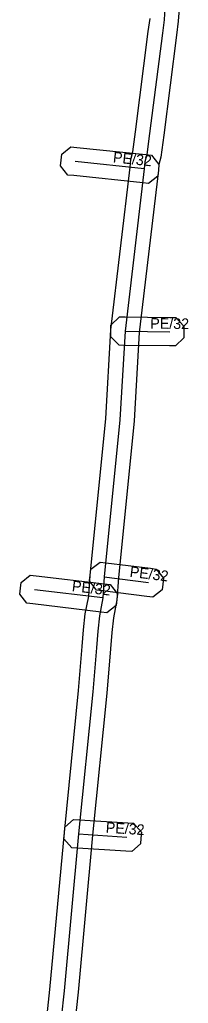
# Model space of a CAD drawing. Extents: x -772893 to -772575, y -1033735 to -1033288.
# Drawn here: x -772743.8 to -772731.9, y -1033432.5 to -1033363.2 of the extents above; entities that cross this region are included whole.
import ezdxf

# ---------------------------------------------------------------- set-up
doc = ezdxf.new("R2010")
doc.units = 0
for name, color, linetype in [('1', 7, 'Continuous'), ('24', 7, 'Continuous'), ('30', 7, 'Continuous')]:
    doc.layers.add(name, color=color, linetype=linetype)

msp = doc.modelspace()

# ---------------------------------------------------------------- linework, layer by layer
at = {"layer": '1'}
for points in [[(-772732.541, -1033362.417), (-772732.603, -1033363.282), (-772732.73, -1033364.269), (-772733.632, -1033371.329), (-772733.83, -1033372.876), (-772733.966, -1033373.389), (-772734.006, -1033373.796), (-772735.353, -1033385.227), (-772735.714, -1033391.464), (-772736.823, -1033402.543), (-772736.926, -1033404.078), (-772737.17, -1033405.353), (-772737.279, -1033406.391), (-772737.374, -1033407.541), (-772737.63, -1033410.653), (-772738.635, -1033420.686), (-772739.654, -1033431.747), (-772740.282, -1033437.549)], [(-772742.27, -1033437.333), (-772741.644, -1033431.547), (-772740.625, -1033420.494), (-772739.622, -1033410.471), (-772739.368, -1033407.377), (-772739.271, -1033406.203), (-772739.15, -1033405.059), (-772738.914, -1033403.822), (-772738.817, -1033402.377), (-772737.708, -1033391.306), (-772737.347, -1033385.053), (-772735.994, -1033373.584), (-772735.942, -1033373.033), (-772735.796, -1033372.49), (-772735.616, -1033371.075), (-772734.714, -1033364.013), (-772734.593, -1033363.084)]]:
    msp.add_lwpolyline(points, dxfattribs=at)
for points in [[(-772734.692, -1033374.728), (-772735.104, -1033374.685), (-772739.964, -1033374.175), (-772740.376, -1033374.132), (-772740.898, -1033373.488), (-772740.855, -1033373.076), (-772740.812, -1033372.664), (-772740.168, -1033372.142), (-772739.756, -1033372.185), (-772734.896, -1033372.695), (-772734.484, -1033372.738), (-772733.962, -1033373.382), (-772734.005, -1033373.794), (-772734.048, -1033374.206)], [(-772736.751, -1033384.135), (-772736.337, -1033384.14), (-772733.197, -1033384.18), (-772732.783, -1033384.185), (-772732.205, -1033384.779), (-772732.21, -1033385.193), (-772732.215, -1033385.607), (-772732.809, -1033386.185), (-772733.223, -1033386.18), (-772736.363, -1033386.14), (-772736.777, -1033386.135), (-772737.355, -1033385.541), (-772737.35, -1033385.127), (-772737.345, -1033384.713)], [(-772738.107, -1033401.417), (-772737.696, -1033401.468), (-772734.566, -1033401.858), (-772734.155, -1033401.909), (-772733.647, -1033402.563), (-772733.698, -1033402.974), (-772733.749, -1033403.385), (-772734.403, -1033403.893), (-772734.814, -1033403.842), (-772737.944, -1033403.452), (-772738.355, -1033403.401), (-772738.863, -1033402.747), (-772738.812, -1033402.336), (-772738.761, -1033401.925)], [(-772737.627, -1033404.992), (-772738.038, -1033404.943), (-772742.848, -1033404.373), (-772743.259, -1033404.324), (-772743.772, -1033403.673), (-772743.723, -1033403.262), (-772743.674, -1033402.851), (-772743.023, -1033402.338), (-772742.612, -1033402.387), (-772737.802, -1033402.957), (-772737.391, -1033403.006), (-772736.878, -1033403.657), (-772736.927, -1033404.068), (-772736.976, -1033404.479)], [(-772739.978, -1033419.565), (-772739.565, -1033419.592), (-772736.165, -1033419.812), (-772735.752, -1033419.839), (-772735.205, -1033420.462), (-772735.232, -1033420.875), (-772735.259, -1033421.288), (-772735.882, -1033421.835), (-772736.295, -1033421.808), (-772739.695, -1033421.588), (-772740.108, -1033421.561), (-772740.655, -1033420.938), (-772740.628, -1033420.525), (-772740.601, -1033420.112)]]:
    msp.add_lwpolyline(points, close=True, dxfattribs=at)
at = {"layer": '24'}
for points in [[(-772733.119, -1033346.272), (-772733.112, -1033346.575), (-772732.924, -1033353.669), (-772733.539, -1033362.346), (-772733.597, -1033363.182), (-772733.722, -1033364.141), (-772734.624, -1033371.202), (-772734.812, -1033372.682), (-772734.954, -1033373.211), (-772735, -1033373.69), (-772736.35, -1033385.14), (-772736.711, -1033391.385), (-772737.82, -1033402.46), (-772737.92, -1033403.95), (-772738.16, -1033405.206), (-772738.274, -1033406.296), (-772738.371, -1033407.459), (-772738.626, -1033410.562), (-772739.63, -1033420.59), (-772740.649, -1033431.647), (-772741.276, -1033437.441)], [(-772735, -1033373.69), (-772739.86, -1033373.18)], [(-772736.35, -1033385.14), (-772733.21, -1033385.18)], [(-772737.82, -1033402.46), (-772734.69, -1033402.85)], [(-772737.92, -1033403.95), (-772742.73, -1033403.38)], [(-772739.63, -1033420.59), (-772736.23, -1033420.81)]]:
    msp.add_lwpolyline(points, dxfattribs=at)

# ---------------------------------------------------------------- texts
at = {"layer": '30'}
for rotation, p in [(354.00941, (-772737.23, -1033373.235)), (359.27016, (-772734.58, -1033384.96)), (352.89751, (-772736.055, -1033402.455)), (353.24179, (-772740.125, -1033403.465)), (356.29779, (-772737.73, -1033420.5))]:
    msp.add_text('PE/32', height=0.75, rotation=rotation, dxfattribs=at).set_placement(p)

doc.saveas('drawing.dxf')
